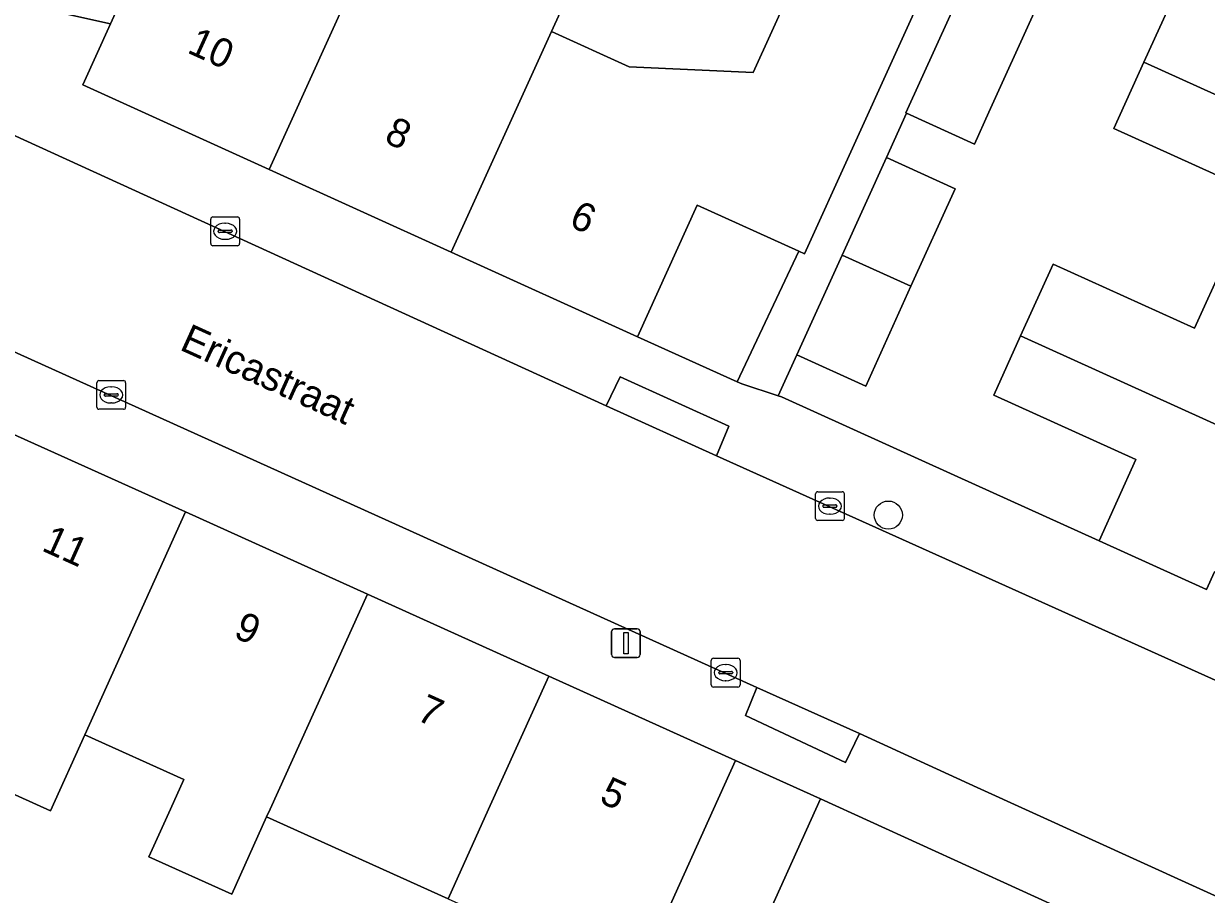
# Model space of a CAD drawing. Extents: x 161838 to 162344, y 381620 to 382160.
# Drawn here: x 162023.71 to 162064.83, y 381747.04 to 381777.31 of the extents above; entities that cross this region are included whole.
import ezdxf

# ---------------------------------------------------------------- set-up
doc = ezdxf.new("R2010")
doc.units = 0
for name, color, linetype in [('IMGEO_Boom', 7, 'Continuous'), ('IMGEO_Erf', 7, 'Continuous'), ('IMGEO_Kolk', 7, 'Continuous'), ('IMGEO_Lichtmast', 7, 'Continuous'), ('IMGEO_Muur', 7, 'Continuous'), ('IMGEO_Openbare_ruimte_label', 7, 'Continuous'), ('IMGEO_Pand', 7, 'Continuous'), ('IMGEO_Pand_nummerreeks', 7, 'Continuous'), ('IMGEO_Rijbaan_lokaal_open', 7, 'Continuous'), ('IMGEO_Voetpad_open', 7, 'Continuous')]:
    doc.layers.add(name, color=color, linetype=linetype)

msp = doc.modelspace()

# ---------------------------------------------------------------- linework, layer by layer
at = {"layer": 'IMGEO_Boom'}
msp.add_circle((162053.769, 381760.227), 0.489, dxfattribs=at)
at = {"layer": 'IMGEO_Erf'}
for points in [[(162032.446, 381790.557), (162032.227, 381790.054), (162038.468, 381787.335), (162037.364, 381784.799), (162031.254, 381787.46), (162029.25, 381782.858), (162035.723, 381779.917), (162036.99, 381782.704), (162043.326, 381779.825), (162042.06, 381777.038), (162044.758, 381775.812), (162049.069, 381775.611), (162051.841, 381781.715)], [(162050.655, 381769.401), (162047.129, 381771.003), (162045.047, 381766.421), (162048.513, 381764.865)]]:
    msp.add_lwpolyline(points, close=True, dxfattribs=at)
for points in [[(162066.546, 381771.429), (162061.613, 381773.671), (162062.654, 381775.972), (162063.703, 381778.29), (162068.645, 381776.051)], [(162058.843, 381777.698), (162057.268, 381774.231), (162056.766, 381773.126), (162054.405, 381774.198), (162053.705, 381772.657), (162056.097, 381771.571), (162054.557, 381768.182), (162052.982, 381764.715), (162050.59, 381765.801), (162049.942, 381764.37), (162050.052, 381764.333), (162056.054, 381761.616), (162061.101, 381759.332), (162062.381, 381762.156), (162057.435, 381764.397), (162058.368, 381766.456), (162059.499, 381768.952), (162064.418, 381766.726), (162065.465, 381769.039)], [(162038.465, 381746.887), (162032.154, 381749.736), (162030.939, 381747.046), (162028.06, 381748.346), (162028.807, 381750), (162029.275, 381751.036), (162025.827, 381752.593), (162024.634, 381749.95), (162018.151, 381752.877), (162019.345, 381755.52), (162013.037, 381758.368), (162012.694, 381757.609), (162009.289, 381758.044), (162007.608, 381744.889)], [(162061.772, 381745.637), (162051.408, 381750.366), (162049.031, 381745.101)]]:
    msp.add_lwpolyline(points, dxfattribs=at)
at = {"layer": 'IMGEO_Kolk'}
for p, q in [((162030.211, 381769.668), (162030.211, 381770.52)), ((162030.286, 381770.594), (162031.138, 381770.594)), ((162031.212, 381770.52), (162031.212, 381769.668)), ((162030.47, 381770.088), (162030.47, 381770.1)), ((162030.908, 381770.051), (162030.51, 381770.051)), ((162030.513, 381770.137), (162030.911, 381770.137)), ((162030.699, 381770.374), (162030.724, 381770.374)), ((162030.954, 381770.1), (162030.954, 381770.088)), ((162030.722, 381769.814), (162030.697, 381769.814)), ((162031.138, 381769.594), (162030.286, 381769.594)), ((162026.25, 381763.979), (162026.25, 381764.831)), ((162026.325, 381764.905), (162027.177, 381764.905)), ((162026.738, 381764.685), (162026.763, 381764.685)), ((162027.251, 381764.831), (162027.251, 381763.979)), ((162026.509, 381764.399), (162026.509, 381764.411)), ((162026.947, 381764.362), (162026.549, 381764.362)), ((162026.552, 381764.448), (162026.95, 381764.448)), ((162026.993, 381764.411), (162026.993, 381764.399)), ((162027.177, 381763.905), (162026.325, 381763.905)), ((162026.761, 381764.125), (162026.736, 381764.125)), ((162051.314, 381761.04), (162052.166, 381761.04)), ((162051.239, 381760.114), (162051.239, 381760.966)), ((162051.541, 381760.583), (162051.939, 381760.583)), ((162051.727, 381760.82), (162051.752, 381760.82)), ((162052.24, 381760.966), (162052.24, 381760.114)), ((162051.498, 381760.534), (162051.498, 381760.546)), ((162051.936, 381760.497), (162051.538, 381760.497)), ((162051.75, 381760.26), (162051.725, 381760.26)), ((162051.982, 381760.546), (162051.982, 381760.534)), ((162052.166, 381760.04), (162051.314, 381760.04)), ((162047.69, 381755.25), (162048.542, 381755.25)), ((162047.615, 381754.324), (162047.615, 381755.176)), ((162048.103, 381755.03), (162048.128, 381755.03)), ((162048.616, 381755.176), (162048.616, 381754.324)), ((162047.874, 381754.744), (162047.874, 381754.756)), ((162048.312, 381754.707), (162047.914, 381754.707)), ((162047.917, 381754.793), (162048.315, 381754.793)), ((162048.126, 381754.47), (162048.101, 381754.47)), ((162048.358, 381754.756), (162048.358, 381754.744)), ((162048.542, 381754.25), (162047.69, 381754.25))]:
    msp.add_line(p, q, dxfattribs=at)
for points in [[(162030.211, 381769.668), (162030.211, 381770.52)], [(162030.286, 381770.594), (162031.138, 381770.594)], [(162031.212, 381770.52), (162031.212, 381769.668)], [(162031.138, 381769.594), (162030.286, 381769.594)], [(162026.25, 381763.979), (162026.25, 381764.831)], [(162026.325, 381764.905), (162027.177, 381764.905)], [(162027.251, 381764.831), (162027.251, 381763.979)], [(162027.177, 381763.905), (162026.325, 381763.905)], [(162051.314, 381761.04), (162052.166, 381761.04)], [(162051.239, 381760.114), (162051.239, 381760.966)], [(162052.24, 381760.966), (162052.24, 381760.114)], [(162052.166, 381760.04), (162051.314, 381760.04)], [(162047.69, 381755.25), (162048.542, 381755.25)], [(162047.615, 381754.324), (162047.615, 381755.176)], [(162048.616, 381755.176), (162048.616, 381754.324)], [(162048.542, 381754.25), (162047.69, 381754.25)]]:
    msp.add_lwpolyline(points, dxfattribs=at)
for centre, radius, start, end in [((162030.288, 381770.518), 0.0765, 91.552, 178.448), ((162030.288, 381770.518), 0.0765, 91.552, 178.448), ((162031.136, 381770.518), 0.0765, 1.552, 88.448), ((162031.136, 381770.518), 0.0765, 1.552, 88.448), ((162030.51, 381770.097), 0.0403, 85.8775, 175.7526), ((162030.507, 381770.087), 0.0366, 178.938, 274.7102), ((162030.911, 381770.094), 0.043, 264.8664, 352.4533), ((162030.915, 381770.099), 0.0386, 1.7309, 96.639), ((162030.288, 381769.67), 0.0765, 181.552, 268.448), ((162030.288, 381769.67), 0.0765, 181.552, 268.448), ((162031.136, 381769.67), 0.0765, 271.552, 358.448), ((162031.136, 381769.67), 0.0765, 271.552, 358.448), ((162026.327, 381764.829), 0.0765, 91.552, 178.448), ((162026.327, 381764.829), 0.0765, 91.552, 178.448), ((162027.175, 381764.829), 0.0765, 1.552, 88.448), ((162027.175, 381764.829), 0.0765, 1.552, 88.448), ((162026.549, 381764.408), 0.0403, 85.8775, 175.7526), ((162026.546, 381764.398), 0.0366, 178.938, 274.7102), ((162026.95, 381764.405), 0.043, 264.8664, 352.4533), ((162026.954, 381764.41), 0.0386, 1.7309, 96.639), ((162026.327, 381763.981), 0.0765, 181.552, 268.448), ((162026.327, 381763.981), 0.0765, 181.552, 268.448), ((162027.175, 381763.981), 0.0765, 271.552, 358.448), ((162027.175, 381763.981), 0.0765, 271.552, 358.448), ((162051.316, 381760.964), 0.0765, 91.552, 178.448), ((162051.316, 381760.964), 0.0765, 91.552, 178.448), ((162052.164, 381760.964), 0.0765, 1.552, 88.448), ((162052.164, 381760.964), 0.0765, 1.552, 88.448), ((162051.538, 381760.543), 0.0403, 85.8775, 175.7526), ((162051.943, 381760.545), 0.0386, 1.7309, 96.639), ((162051.535, 381760.533), 0.0366, 178.938, 274.7102), ((162051.939, 381760.54), 0.043, 264.8664, 352.4533), ((162051.316, 381760.116), 0.0765, 181.552, 268.448), ((162051.316, 381760.116), 0.0765, 181.552, 268.448), ((162052.164, 381760.116), 0.0765, 271.552, 358.448), ((162052.164, 381760.116), 0.0765, 271.552, 358.448), ((162047.692, 381755.174), 0.0765, 91.552, 178.448), ((162047.692, 381755.174), 0.0765, 91.552, 178.448), ((162048.54, 381755.174), 0.0765, 1.552, 88.448), ((162048.54, 381755.174), 0.0765, 1.552, 88.448), ((162047.914, 381754.753), 0.0403, 85.8775, 175.7526), ((162047.911, 381754.743), 0.0366, 178.938, 274.7102), ((162048.315, 381754.75), 0.043, 264.8664, 352.4533), ((162048.319, 381754.755), 0.0386, 1.7309, 96.639), ((162047.692, 381754.326), 0.0765, 181.552, 268.448), ((162047.692, 381754.326), 0.0765, 181.552, 268.448), ((162048.54, 381754.326), 0.0765, 271.552, 358.448), ((162048.54, 381754.326), 0.0765, 271.552, 358.448)]:
    msp.add_arc(centre, radius, start, end, dxfattribs=at)
for centre, major_axis, ratio, start_param, end_param in [((162030.698, 381770.094), (-0.387, 0.002), 0.722429, 4.712389, 7.853982), ((162030.723, 381770.094), (-0.39, 0.002), 0.717154, 1.570796, 4.712389), ((162026.737, 381764.405), (-0.387, 0.002), 0.722429, 4.712389, 7.853982), ((162026.762, 381764.405), (-0.39, 0.002), 0.717154, 1.570796, 4.712389), ((162051.726, 381760.54), (-0.387, 0.002), 0.722429, 4.712389, 7.853982), ((162051.751, 381760.54), (-0.39, 0.002), 0.717154, 1.570796, 4.712389), ((162048.102, 381754.75), (-0.387, 0.002), 0.722429, 4.712389, 7.853982), ((162048.127, 381754.75), (-0.39, 0.002), 0.717154, 1.570796, 4.712389)]:
    msp.add_ellipse(centre, major_axis=major_axis, ratio=ratio, start_param=start_param, end_param=end_param, dxfattribs=at)
at = {"layer": 'IMGEO_Lichtmast'}
for p, q in [((162044.15, 381755.375), (162044.15, 381756.175)), ((162044.15, 381756.175), (162044.15, 381755.375)), ((162044.25, 381756.275), (162045.04, 381756.275)), ((162045.04, 381756.275), (162044.25, 381756.275)), ((162045.14, 381756.175), (162045.14, 381755.375)), ((162045.14, 381755.375), (162045.14, 381756.175)), ((162045.04, 381755.275), (162044.25, 381755.275)), ((162044.25, 381755.275), (162045.04, 381755.275))]:
    msp.add_line(p, q, dxfattribs=at)
msp.add_lwpolyline([(162044.57, 381756.15), (162044.72, 381756.15), (162044.72, 381755.4), (162044.57, 381755.4), (162044.57, 381756.15)], dxfattribs=at)
for centre, start, end in [((162044.25, 381756.175), 90, 180), ((162044.25, 381756.175), 90, 180), ((162045.04, 381756.175), 0, 90), ((162045.04, 381756.175), 360, 90), ((162044.25, 381755.375), 180, 270), ((162044.25, 381755.375), 180, 270), ((162045.04, 381755.375), 270, 0), ((162045.04, 381755.375), 270, 0)]:
    msp.add_arc(centre, 0.1, start, end, dxfattribs=at)
at = {"layer": 'IMGEO_Muur'}
for points in [[(162061.101, 381759.332), (162056.054, 381761.616)], [(162061.772, 381745.637), (162051.408, 381750.366)]]:
    msp.add_lwpolyline(points, dxfattribs=at)
at = {"layer": 'IMGEO_Pand'}
for points in [[(162032.236, 381772.242), (162035.723, 381779.917), (162029.25, 381782.858), (162027.831, 381779.736), (162026.727, 381777.305), (162025.763, 381775.183)], [(162032.236, 381772.242), (162038.572, 381769.363), (162042.06, 381777.038), (162043.326, 381779.825), (162036.99, 381782.704), (162035.723, 381779.917)], [(162051.841, 381781.715), (162049.069, 381775.611), (162044.758, 381775.812), (162042.06, 381777.038), (162038.572, 381769.363), (162045.047, 381766.421), (162047.129, 381771.003), (162050.655, 381769.401), (162050.853, 381769.311), (162055.694, 381779.965)], [(162058.843, 381777.698), (162056.45, 381778.782), (162054.374, 381774.212), (162054.405, 381774.198), (162056.766, 381773.126), (162057.268, 381774.231)], [(162075.797, 381775.863), (162069.789, 381778.584), (162068.645, 381776.051), (162063.703, 381778.29), (162062.654, 381775.972), (162073.603, 381771.013)], [(162065.465, 381769.039), (162071.478, 381766.316), (162073.603, 381771.013), (162062.654, 381775.972), (162061.613, 381773.671), (162066.546, 381771.429)], [(162054.557, 381768.182), (162056.097, 381771.571), (162053.705, 381772.657), (162052.164, 381769.266)], [(162054.557, 381768.182), (162052.164, 381769.266), (162050.59, 381765.801), (162052.982, 381764.715)], [(162069.301, 381761.504), (162071.478, 381766.316), (162065.465, 381769.039), (162064.418, 381766.726), (162059.499, 381768.952), (162058.368, 381766.456)], [(162069.301, 381761.504), (162058.368, 381766.456), (162057.435, 381764.397), (162062.381, 381762.156), (162061.101, 381759.332), (162064.835, 381757.639), (162065.115, 381758.257), (162067.371, 381757.236), (162067.446, 381757.401)], [(162029.328, 381760.335), (162023.027, 381763.18), (162019.526, 381755.438), (162019.345, 381755.52), (162018.151, 381752.877), (162024.634, 381749.95), (162025.827, 381752.593)], [(162035.655, 381757.478), (162029.328, 381760.335), (162025.827, 381752.593), (162029.275, 381751.036), (162028.807, 381750), (162028.06, 381748.346), (162030.939, 381747.046), (162032.154, 381749.736), (162032.273, 381750)], [(162038.465, 381746.887), (162039.873, 381750), (162041.966, 381754.629), (162035.655, 381757.478), (162032.273, 381750), (162032.154, 381749.736)], [(162044.624, 381743.216), (162046.08, 381746.435), (162047.692, 381750), (162048.46, 381751.697), (162041.966, 381754.629), (162039.873, 381750), (162038.465, 381746.887), (162044.858, 381744), (162044.525, 381743.261)], [(162048.46, 381751.697), (162047.692, 381750), (162046.08, 381746.435), (162049.031, 381745.101), (162051.408, 381750.366)]]:
    msp.add_lwpolyline(points, close=True, dxfattribs=at)
at = {"layer": 'IMGEO_Rijbaan_lokaal_open'}
msp.add_lwpolyline([(162015.372, 381769.412), (162017.318, 381768.637), (162049.197, 381754.238), (162052.77, 381752.631), (162056.86, 381750.762), (162068.214, 381745.584), (162068.985, 381745.23), (162081.324, 381741.038), (162082.15, 381740.62), (162087.294, 381738.315), (162101.774, 381731.795), (162101.956, 381731.713), (162103.87, 381735.811), (162103.292, 381736.059), (162084.495, 381744.526), (162081.506, 381746.115), (162073.51, 381750.574), (162071.642, 381751.481), (162071.089, 381751.71), (162069.847, 381752.372), (162047.793, 381762.29), (162043.964, 381764.024), (162019.542, 381775.175)], dxfattribs=at)
at = {"layer": 'IMGEO_Voetpad_open'}
for points in [[(162074.49, 381753.282), (162068.219, 381756.057), (162068.579, 381756.936), (162067.446, 381757.401), (162067.371, 381757.236), (162065.115, 381758.257), (162064.835, 381757.639), (162061.101, 381759.332), (162056.054, 381761.616), (162050.052, 381764.333), (162049.942, 381764.37), (162048.674, 381764.793), (162048.513, 381764.865), (162045.047, 381766.421), (162038.572, 381769.363), (162032.236, 381772.242), (162025.763, 381775.183), (162026.727, 381777.305), (162025.108, 381777.668), (162022.125, 381778.338), (162018.222, 381779.214), (162009.992, 381781.058), (162007.821, 381781.474), (162004.221, 381782.086)], [(162055.694, 381779.965), (162050.853, 381769.311), (162050.655, 381769.401), (162048.513, 381764.865), (162048.674, 381764.793), (162049.942, 381764.37), (162050.59, 381765.801), (162052.164, 381769.266), (162053.705, 381772.657), (162054.405, 381774.198), (162054.374, 381774.212), (162056.45, 381778.782)], [(162025.108, 381777.668), (162026.727, 381777.305), (162027.831, 381779.736)], [(162010.464, 381769.821), (162010.639, 381770.93), (162008.503, 381771.36), (161974.338, 381775.707), (161974.073, 381772.99), (162000, 381769.681), (162008.257, 381768.648), (162008.135, 381767.624), (162007.766, 381764.735), (162010.108, 381764.458), (162015.212, 381763.807), (162016.3, 381766.217), (162023.027, 381763.18), (162029.328, 381760.335), (162035.655, 381757.478), (162041.966, 381754.629), (162048.46, 381751.697), (162051.408, 381750.366), (162061.772, 381745.637), (162069.369, 381742.199), (162071.683, 381741.12)], [(162019.542, 381775.175), (162043.964, 381764.024), (162044.441, 381765.033), (162048.229, 381763.319), (162047.793, 381762.29), (162069.847, 381752.372), (162071.089, 381751.71), (162071.642, 381751.481), (162073.51, 381750.574), (162073.964, 381751.536), (162076.538, 381750.111), (162077.557, 381752.046), (162077.753, 381752.48), (162074.49, 381753.282)], [(162068.985, 381745.23), (162068.214, 381745.584), (162056.86, 381750.762), (162052.77, 381752.631), (162052.283, 381751.622), (162048.804, 381753.263), (162049.197, 381754.238), (162017.318, 381768.637), (162015.372, 381769.412), (162014.939, 381768.441)]]:
    msp.add_lwpolyline(points, dxfattribs=at)
for points in [[(162047.793, 381762.29), (162048.229, 381763.319), (162044.441, 381765.033), (162043.964, 381764.024)], [(162052.77, 381752.631), (162049.197, 381754.238), (162048.804, 381753.263), (162052.283, 381751.622)]]:
    msp.add_lwpolyline(points, close=True, dxfattribs=at)

# ---------------------------------------------------------------- texts
at = {"layer": 'IMGEO_Openbare_ruimte_label'}
msp.add_text('Ericastraat', height=1, rotation=335.6129, dxfattribs=at).set_placement((162029.09, 381765.992))
at = {"layer": 'IMGEO_Pand_nummerreeks'}
for s, rotation, p in [('10', 335.5646, (162029.353, 381776.32)), ('8', 335.5646, (162036.201, 381773.209)), ('6', 335.5634, (162042.626, 381770.29)), ('11', 335.7009, (162024.291, 381759.01)), ('9', 335.7012, (162030.963, 381755.998)), ('7', 335.7012, (162037.321, 381753.127)), ('5', 335.7012, (162043.68, 381750.256))]:
    msp.add_text(s, height=1, rotation=rotation, dxfattribs=at).set_placement(p)

doc.saveas('drawing.dxf')
